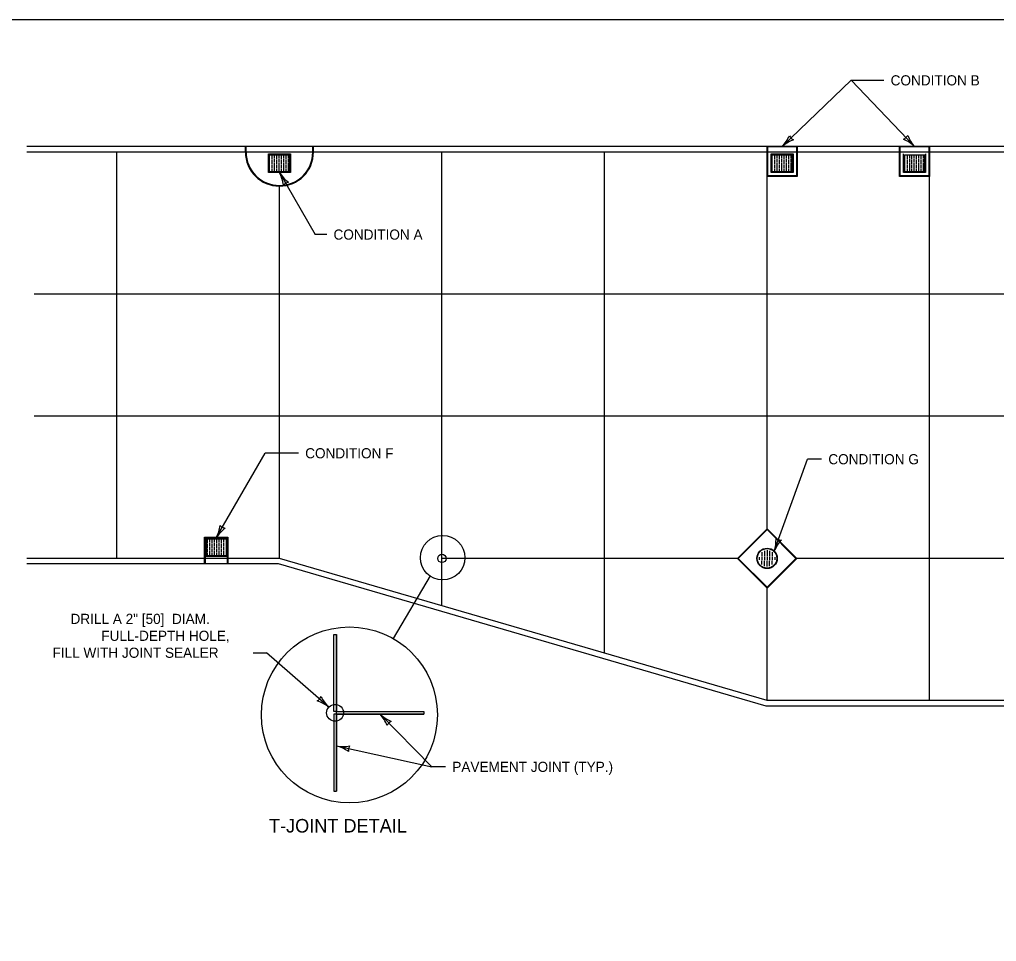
# Model space of a CAD drawing. Extents: x 49991.4 to 50029.7, y 49987.6 to 50011.4.
# Drawn here: x 49999.92 to 50005.69, y 49993.55 to 49999 of the extents above; entities that cross this region are included whole.
import ezdxf

# ---------------------------------------------------------------- set-up
doc = ezdxf.new("R2010")
doc.units = 0
for name, color, linetype in [('Level 1', 7, 'Continuous'), ('Level 18', 7, 'Continuous'), ('Level 2', 7, 'Continuous'), ('Level 3', 7, 'Continuous'), ('Level 62', 7, 'Continuous')]:
    doc.layers.add(name, color=color, linetype=linetype)

msp = doc.modelspace()

# ---------------------------------------------------------------- linework, layer by layer
at = {"layer": 'Level 1'}
for p, q in [((50005.8148, 49998.2482), (49999.9583, 49998.2482)), ((50005.8148, 49998.2157), (49999.9583, 49998.2157)), ((50000.4908, 49995.8157), (50000.4908, 49998.2157)), ((50001.25, 49998.2157), (50001.25, 49998.2482)), ((50001.2538, 49998.2157), (50001.2538, 49998.2482)), ((50001.6478, 49998.2157), (50001.6478, 49998.2482)), ((50001.6515, 49998.2157), (50001.6515, 49998.2482)), ((50002.4108, 49995.5357), (50002.4108, 49998.2157)), ((50003.3708, 49995.2557), (50003.3708, 49998.2157)), ((50004.3308, 49995.991), (50004.3308, 49998.2157)), ((50005.2908, 49994.9757), (50005.2908, 49998.2482)), ((50001.3858, 49998.0951), (50001.3858, 49998.2051)), ((50001.3858, 49998.2051), (50001.5158, 49998.2051)), ((50001.3901, 49998.2007), (50001.3901, 49998.0995)), ((50001.3908, 49998.1999), (50001.3901, 49998.2007)), ((50001.5114, 49998.2007), (50001.3901, 49998.2007)), ((50001.5108, 49998.1999), (50001.3908, 49998.1999)), ((50001.4063, 49998.1943), (50001.4063, 49998.1718)), ((50001.4063, 49998.1681), (50001.4063, 49998.1468)), ((50001.4199, 49998.1943), (50001.4199, 49998.1818)), ((50001.4199, 49998.178), (50001.4199, 49998.1568)), ((50001.4335, 49998.1943), (50001.4335, 49998.1718)), ((50001.4335, 49998.1681), (50001.4335, 49998.1468)), ((50001.4471, 49998.1943), (50001.4471, 49998.1818)), ((50001.4471, 49998.178), (50001.4471, 49998.1568)), ((50001.4607, 49998.1943), (50001.4607, 49998.1718)), ((50001.4607, 49998.1681), (50001.4607, 49998.1468)), ((50001.4743, 49998.1943), (50001.4743, 49998.1818)), ((50001.4743, 49998.178), (50001.4743, 49998.1568)), ((50001.4878, 49998.1943), (50001.4878, 49998.1718)), ((50001.4878, 49998.1681), (50001.4878, 49998.1468)), ((50001.5014, 49998.1943), (50001.5014, 49998.1818)), ((50001.5014, 49998.178), (50001.5014, 49998.1568)), ((50001.5114, 49998.2007), (50001.5108, 49998.1999)), ((50001.5108, 49998.0999), (50001.5108, 49998.1999)), ((50001.5114, 49998.0995), (50001.5114, 49998.2007)), ((50001.5158, 49998.2051), (50001.5158, 49998.0951)), ((50004.3545, 49998.0951), (50004.3545, 49998.2051)), ((50004.3545, 49998.2051), (50004.4845, 49998.2051)), ((50004.3589, 49998.2007), (50004.3589, 49998.0995)), ((50004.3595, 49998.1999), (50004.3589, 49998.2007)), ((50004.4801, 49998.2007), (50004.3589, 49998.2007)), ((50004.3751, 49998.1943), (50004.3751, 49998.1718)), ((50004.3751, 49998.1681), (50004.3751, 49998.1468)), ((50004.3886, 49998.1943), (50004.3886, 49998.1818)), ((50004.3886, 49998.178), (50004.3886, 49998.1568)), ((50004.4022, 49998.1943), (50004.4022, 49998.1718)), ((50004.4022, 49998.1681), (50004.4022, 49998.1468)), ((50004.4158, 49998.1943), (50004.4158, 49998.1818)), ((50004.4158, 49998.178), (50004.4158, 49998.1568)), ((50004.4294, 49998.1943), (50004.4294, 49998.1718)), ((50004.4294, 49998.1681), (50004.4294, 49998.1468)), ((50004.443, 49998.1943), (50004.443, 49998.1818)), ((50004.443, 49998.178), (50004.443, 49998.1568)), ((50004.4566, 49998.1943), (50004.4566, 49998.1718)), ((50004.4566, 49998.1681), (50004.4566, 49998.1468)), ((50004.4702, 49998.1943), (50004.4702, 49998.1818)), ((50004.4702, 49998.178), (50004.4702, 49998.1568)), ((50004.4801, 49998.2007), (50004.4795, 49998.1999)), ((50004.4795, 49998.0999), (50004.4795, 49998.1999)), ((50004.4801, 49998.0995), (50004.4801, 49998.2007)), ((50004.4845, 49998.2051), (50004.4845, 49998.0951)), ((50005.137, 49998.0951), (50005.137, 49998.2051)), ((50005.1414, 49998.2007), (50005.1414, 49998.0995)), ((50005.1576, 49998.1943), (50005.1576, 49998.1718)), ((50005.1576, 49998.1681), (50005.1576, 49998.1468)), ((50005.1711, 49998.1943), (50005.1711, 49998.1818)), ((50005.1711, 49998.178), (50005.1711, 49998.1568)), ((50005.1847, 49998.1943), (50005.1847, 49998.1718)), ((50005.1847, 49998.1681), (50005.1847, 49998.1468)), ((50005.1983, 49998.1943), (50005.1983, 49998.1818)), ((50005.1983, 49998.178), (50005.1983, 49998.1568)), ((50005.2119, 49998.1943), (50005.2119, 49998.1718)), ((50005.2119, 49998.1681), (50005.2119, 49998.1468)), ((50005.2255, 49998.1943), (50005.2255, 49998.1818)), ((50005.2255, 49998.178), (50005.2255, 49998.1568)), ((50005.2391, 49998.1943), (50005.2391, 49998.1718)), ((50005.2391, 49998.1681), (50005.2391, 49998.1468)), ((50005.2527, 49998.1943), (50005.2527, 49998.1818)), ((50005.2527, 49998.178), (50005.2527, 49998.1568)), ((50005.262, 49998.0999), (50005.262, 49998.1999)), ((50005.2626, 49998.0995), (50005.2626, 49998.2007)), ((50005.267, 49998.2051), (50005.267, 49998.0951)), ((50001.3908, 49998.0999), (50001.3901, 49998.0995)), ((50001.3901, 49998.0995), (50001.5114, 49998.0995)), ((50001.3908, 49998.0999), (50001.5108, 49998.0999)), ((50001.4063, 49998.1431), (50001.4063, 49998.1218)), ((50001.4063, 49998.1181), (50001.4063, 49998.1056)), ((50001.4199, 49998.1531), (50001.4199, 49998.1318)), ((50001.4199, 49998.1281), (50001.4199, 49998.1056)), ((50001.4335, 49998.1431), (50001.4335, 49998.1218)), ((50001.4335, 49998.1181), (50001.4335, 49998.1056)), ((50001.4471, 49998.1531), (50001.4471, 49998.1318)), ((50001.4471, 49998.1281), (50001.4471, 49998.1056)), ((50001.4607, 49998.1431), (50001.4607, 49998.1218)), ((50001.4607, 49998.1181), (50001.4607, 49998.1056)), ((50001.4743, 49998.1531), (50001.4743, 49998.1318)), ((50001.4743, 49998.1281), (50001.4743, 49998.1056)), ((50001.4876, 49998.0995), (50001.5101, 49998.0995)), ((50001.4878, 49998.1431), (50001.4878, 49998.1218)), ((50001.4878, 49998.1181), (50001.4878, 49998.1056)), ((50001.5014, 49998.1531), (50001.5014, 49998.1318)), ((50001.5014, 49998.1281), (50001.5014, 49998.1056)), ((50001.5114, 49998.0995), (50001.5108, 49998.0999)), ((50004.3595, 49998.0999), (50004.3589, 49998.0995)), ((50004.3589, 49998.0995), (50004.4801, 49998.0995)), ((50004.3595, 49998.0999), (50004.4795, 49998.0999)), ((50004.3751, 49998.1431), (50004.3751, 49998.1218)), ((50004.3751, 49998.1181), (50004.3751, 49998.1056)), ((50004.3886, 49998.1531), (50004.3886, 49998.1318)), ((50004.3886, 49998.1281), (50004.3886, 49998.1056)), ((50004.4022, 49998.1431), (50004.4022, 49998.1218)), ((50004.4022, 49998.1181), (50004.4022, 49998.1056)), ((50004.4158, 49998.1531), (50004.4158, 49998.1318)), ((50004.4158, 49998.1281), (50004.4158, 49998.1056)), ((50004.4294, 49998.1431), (50004.4294, 49998.1218)), ((50004.4294, 49998.1181), (50004.4294, 49998.1056)), ((50004.443, 49998.1531), (50004.443, 49998.1318)), ((50004.443, 49998.1281), (50004.443, 49998.1056)), ((50004.4563, 49998.0995), (50004.4789, 49998.0995)), ((50004.4566, 49998.1431), (50004.4566, 49998.1218)), ((50004.4566, 49998.1181), (50004.4566, 49998.1056)), ((50004.4702, 49998.1531), (50004.4702, 49998.1318)), ((50004.4702, 49998.1281), (50004.4702, 49998.1056)), ((50004.4801, 49998.0995), (50004.4795, 49998.0999)), ((50005.142, 49998.0999), (50005.1414, 49998.0995)), ((50005.1414, 49998.0995), (50005.2626, 49998.0995)), ((50005.142, 49998.0999), (50005.262, 49998.0999)), ((50005.1576, 49998.1431), (50005.1576, 49998.1218)), ((50005.1576, 49998.1181), (50005.1576, 49998.1056)), ((50005.1711, 49998.1531), (50005.1711, 49998.1318)), ((50005.1711, 49998.1281), (50005.1711, 49998.1056)), ((50005.1847, 49998.1431), (50005.1847, 49998.1218)), ((50005.1847, 49998.1181), (50005.1847, 49998.1056)), ((50005.1983, 49998.1531), (50005.1983, 49998.1318)), ((50005.1983, 49998.1281), (50005.1983, 49998.1056)), ((50005.2119, 49998.1431), (50005.2119, 49998.1218)), ((50005.2119, 49998.1181), (50005.2119, 49998.1056)), ((50005.2255, 49998.1531), (50005.2255, 49998.1318)), ((50005.2255, 49998.1281), (50005.2255, 49998.1056)), ((50005.2388, 49998.0995), (50005.2614, 49998.0995)), ((50005.2391, 49998.1431), (50005.2391, 49998.1218)), ((50005.2391, 49998.1181), (50005.2391, 49998.1056)), ((50005.2527, 49998.1531), (50005.2527, 49998.1318)), ((50005.2527, 49998.1281), (50005.2527, 49998.1056)), ((50005.2626, 49998.0995), (50005.262, 49998.0999)), ((50001.5158, 49998.0951), (50001.3858, 49998.0951)), ((50004.4845, 49998.0951), (50004.3545, 49998.0951)), ((50005.267, 49998.0951), (50005.137, 49998.0951)), ((50001.4508, 49995.8157), (50001.4508, 49998.015)), ((50016.2033, 49997.3757), (50000.0029, 49997.3757)), ((50011.8945, 49996.6557), (50000.0029, 49996.6557)), ((50001.0086, 49995.7832), (50001.0086, 49995.9401)), ((50001.0086, 49995.9401), (50001.1461, 49995.9401)), ((50001.0124, 49995.8264), (50001.0124, 49995.9363)), ((50001.0124, 49995.9363), (50001.1424, 49995.9363)), ((50001.0167, 49995.932), (50001.0174, 49995.9315)), ((50001.0167, 49995.932), (50001.0167, 49995.8307)), ((50001.138, 49995.932), (50001.0167, 49995.932)), ((50001.0174, 49995.9315), (50001.0174, 49995.8315)), ((50001.1374, 49995.9315), (50001.0174, 49995.9315)), ((50001.0406, 49995.932), (50001.018, 49995.932)), ((50001.0267, 49995.9034), (50001.0267, 49995.9259)), ((50001.0403, 49995.9134), (50001.0403, 49995.9259)), ((50001.0403, 49995.8884), (50001.0403, 49995.9096)), ((50001.0539, 49995.9034), (50001.0539, 49995.9259)), ((50001.0675, 49995.9134), (50001.0675, 49995.9259)), ((50001.0675, 49995.8884), (50001.0675, 49995.9096)), ((50001.0811, 49995.9034), (50001.0811, 49995.9259)), ((50001.0946, 49995.9134), (50001.0946, 49995.9259)), ((50001.0946, 49995.8884), (50001.0946, 49995.9096)), ((50001.1082, 49995.9034), (50001.1082, 49995.9259)), ((50001.1218, 49995.9134), (50001.1218, 49995.9259)), ((50001.1218, 49995.8884), (50001.1218, 49995.9096)), ((50001.1374, 49995.9315), (50001.138, 49995.932)), ((50001.138, 49995.8307), (50001.138, 49995.932)), ((50001.1424, 49995.9363), (50001.1424, 49995.8264)), ((50001.1461, 49995.9401), (50001.1461, 49995.7832)), ((50001.0267, 49995.8784), (50001.0267, 49995.8996)), ((50001.0267, 49995.8534), (50001.0267, 49995.8746)), ((50001.0267, 49995.8372), (50001.0267, 49995.8497)), ((50001.0403, 49995.8634), (50001.0403, 49995.8846)), ((50001.0403, 49995.8372), (50001.0403, 49995.8597)), ((50001.0539, 49995.8784), (50001.0539, 49995.8996)), ((50001.0539, 49995.8534), (50001.0539, 49995.8746)), ((50001.0539, 49995.8372), (50001.0539, 49995.8497)), ((50001.0675, 49995.8634), (50001.0675, 49995.8846)), ((50001.0675, 49995.8372), (50001.0675, 49995.8597)), ((50001.0811, 49995.8784), (50001.0811, 49995.8996)), ((50001.0811, 49995.8534), (50001.0811, 49995.8746)), ((50001.0811, 49995.8372), (50001.0811, 49995.8497)), ((50001.0946, 49995.8634), (50001.0946, 49995.8846)), ((50001.0947, 49995.8372), (50001.0947, 49995.8597)), ((50001.1082, 49995.8784), (50001.1082, 49995.8996)), ((50001.1082, 49995.8534), (50001.1082, 49995.8746)), ((50001.1082, 49995.8372), (50001.1082, 49995.8497)), ((50001.1218, 49995.8634), (50001.1218, 49995.8846)), ((50001.1218, 49995.8372), (50001.1218, 49995.8597)), ((50004.3001, 49995.8522), (50004.3001, 49995.8311)), ((50004.3154, 49995.8611), (50004.3154, 49995.8311)), ((50004.3308, 49995.8638), (50004.3308, 49995.8311)), ((50004.3461, 49995.8611), (50004.3461, 49995.8311)), ((50004.3614, 49995.8522), (50004.3614, 49995.8311)), ((50001.4508, 49995.8157), (49999.9583, 49995.8157)), ((50001.1424, 49995.8264), (50001.0124, 49995.8264)), ((50001.0124, 49995.8264), (50001.0124, 49995.7832)), ((50001.0167, 49995.8307), (50001.0174, 49995.8315)), ((50001.0167, 49995.8307), (50001.138, 49995.8307)), ((50001.1374, 49995.8315), (50001.138, 49995.8307)), ((50001.1424, 49995.8264), (50001.1424, 49995.7832)), ((50004.3308, 49994.9757), (50001.4508, 49995.8157)), ((50004.1554, 49995.8157), (50002.4108, 49995.8157)), ((50004.2848, 49995.8237), (50004.2848, 49995.8077)), ((50004.3001, 49995.8267), (50004.3001, 49995.8048)), ((50004.3001, 49995.7793), (50004.3001, 49995.8004)), ((50004.3154, 49995.8267), (50004.3154, 49995.8048)), ((50004.3154, 49995.7704), (50004.3154, 49995.8004)), ((50004.3308, 49995.8267), (50004.3308, 49995.8048)), ((50004.3308, 49995.7677), (50004.3308, 49995.8004)), ((50004.3461, 49995.8267), (50004.3461, 49995.8048)), ((50004.3461, 49995.7704), (50004.3461, 49995.8004)), ((50004.3614, 49995.8267), (50004.3614, 49995.8048)), ((50004.3614, 49995.7793), (50004.3614, 49995.8004)), ((50004.3767, 49995.8237), (50004.3767, 49995.8077)), ((50007.0905, 49995.8157), (50004.5061, 49995.8157)), ((50001.4461, 49995.7832), (49999.9583, 49995.7832)), ((50004.3261, 49994.9432), (50001.4461, 49995.7832)), ((50004.3308, 49994.9757), (50004.3308, 49995.6404)), ((50001.7718, 49994.9109), (50001.7718, 49995.3656)), ((50001.7874, 49994.9109), (50001.7874, 49995.3656)), ((50016.2033, 49994.9432), (50004.3261, 49994.9432)), ((50016.2033, 49994.9757), (50004.3308, 49994.9757)), ((50001.7718, 49994.8952), (50001.7718, 49994.4404)), ((50001.7874, 49994.9109), (50002.3028, 49994.9109)), ((50001.7874, 49994.8952), (50002.3028, 49994.8952)), ((50001.7874, 49994.8952), (50001.7874, 49994.4404))]:
    msp.add_line(p, q, dxfattribs=at)
for points in [[(49999.3835, 49998.9992), (50016.7501, 49998.9992), (50016.7501, 49987.7988), (49999.3835, 49987.7988)], [(50004.3308, 49998.2482), (50004.5083, 49998.2482), (50004.5083, 49998.0714), (50004.3308, 49998.0714)], [(50004.3345, 49998.2482), (50004.5045, 49998.2482), (50004.5045, 49998.0751), (50004.3345, 49998.0751)], [(50005.1133, 49998.2482), (50005.2908, 49998.2482), (50005.2908, 49998.0714), (50005.1133, 49998.0714)], [(50005.117, 49998.2482), (50005.287, 49998.2482), (50005.287, 49998.0751), (50005.117, 49998.0751)], [(50001.3908, 49998.1999), (50001.5107, 49998.1999), (50001.5107, 49998.0999), (50001.3908, 49998.0999)], [(50004.3595, 49998.1999), (50004.4795, 49998.1999), (50004.4795, 49998.0999), (50004.3595, 49998.0999)], [(50005.142, 49998.1999), (50005.262, 49998.1999), (50005.262, 49998.0999), (50005.142, 49998.0999)], [(50004.3308, 49995.991), (50004.5061, 49995.8157), (50004.3308, 49995.6404), (50004.1554, 49995.8157)], [(50004.3308, 49995.9857), (50004.5008, 49995.8157), (50004.3308, 49995.6457), (50004.1607, 49995.8157)], [(50001.1374, 49995.8315), (50001.0174, 49995.8315), (50001.0174, 49995.9315), (50001.1374, 49995.9315)], [(50001.7718, 49995.3656), (50001.7874, 49995.3656), (50001.7874, 49994.9109), (50001.7718, 49994.9109)], [(50001.7718, 49994.4404), (50001.7874, 49994.4404), (50001.7874, 49994.8952), (50001.7718, 49994.8952)], [(50002.3028, 49994.8952), (50001.7874, 49994.8952), (50001.7874, 49994.9109), (50002.3028, 49994.9109)]]:
    msp.add_lwpolyline(points, close=True, dxfattribs=at)
for centre, radius in [((50004.3308, 49995.8157), 0.0602), ((50004.3308, 49995.8157), 0.0577), ((50001.7796, 49994.903), 0.05)]:
    msp.add_circle(centre, radius, dxfattribs=at)
for radius in [0.2008, 0.197]:
    msp.add_arc((50001.4508, 49998.2157), radius, 180, 0, dxfattribs=at)
at = {"layer": 'Level 18'}
for p, q in [((50001.3908, 49998.1999), (50001.3908, 49998.0999)), ((50004.4795, 49998.1999), (50004.3595, 49998.1999)), ((50004.3595, 49998.1999), (50004.3595, 49998.0999)), ((50005.142, 49998.1999), (50005.142, 49998.0999)), ((50001.3858, 49998.0951), (50001.3858, 49998.0951)), ((50001.5158, 49998.0951), (50001.5158, 49998.0951)), ((50004.3545, 49998.0951), (50004.3545, 49998.0951)), ((50004.4845, 49998.0951), (50004.4845, 49998.0951)), ((50005.137, 49998.0951), (50005.137, 49998.0951)), ((50005.267, 49998.0951), (50005.267, 49998.0951)), ((50001.0124, 49995.9363), (50001.0124, 49995.9363)), ((50001.1374, 49995.8315), (50001.1374, 49995.9315)), ((50001.1424, 49995.9363), (50001.1424, 49995.9363)), ((50001.0174, 49995.8315), (50001.1374, 49995.8315))]:
    msp.add_line(p, q, dxfattribs=at)
at = {"layer": 'Level 3'}
for p, q in [((50004.8274, 49998.64), (50005.0206, 49998.64)), ((50001.4508, 49998.0951), (50001.6623, 49997.7288)), ((50001.7301, 49997.7288), (50001.6623, 49997.7288)), ((50001.0774, 49995.9363), (50001.3663, 49996.4368)), ((50001.5628, 49996.4368), (50001.3663, 49996.4368)), ((50004.3733, 49995.8583), (50004.5704, 49996.4016)), ((50004.6525, 49996.4016), (50004.5704, 49996.4016)), ((50002.3419, 49995.7121), (50002.1217, 49995.342)), ((50001.2952, 49995.2583), (50001.3752, 49995.2583)), ((50001.7423, 49994.9364), (50001.3752, 49995.2583)), ((50002.3516, 49994.5842), (50002.0451, 49994.8952)), ((50001.7874, 49994.7073), (50002.3516, 49994.5842)), ((50002.4316, 49994.5842), (50002.3516, 49994.5842))]:
    msp.add_line(p, q, dxfattribs=at)
msp.add_lwpolyline([(50004.4195, 49998.2482), (50004.8274, 49998.64), (50005.202, 49998.2482)], dxfattribs=at)
for centre, radius in [((50002.4147, 49995.8195), 0.1314), ((50001.8639, 49994.8912), 0.5198)]:
    msp.add_circle(centre, radius, dxfattribs=at)
for centre, radius, start, end in [((50004.25, 49998.4081), 0.233, 316.67449, 335.92434), ((50004.5668, 49998.0817), 0.2223, 111.30319, 131.4867), ((50004.512, 49998.337), 0.0548, 205.986, 241.70836), ((50005.1134, 49998.3409), 0.0548, 295.85488, 331.57724), ((50005.0418, 49998.0791), 0.233, 46.54337, 65.79322), ((50005.3689, 49998.3951), 0.2223, 201.17207, 221.35558), ((50001.2538, 49997.992), 0.2223, 7.45601, 27.63952), ((50001.6466, 49998.2214), 0.233, 212.82731, 232.07716), ((50001.5149, 49997.9841), 0.0548, 102.13882, 137.86118), ((50000.8701, 49996.0427), 0.233, 332.82732, 352.07717), ((50001.2652, 49995.8173), 0.2223, 127.45602, 147.63953), ((50001.1415, 49996.0474), 0.0548, 222.13883, 257.86119), ((50004.1507, 49995.9268), 0.233, 342.89595, 2.1458), ((50004.5791, 49995.774), 0.2223, 137.52465, 157.70816), ((50004.4171, 49995.9788), 0.0548, 232.20746, 267.92982), ((50001.6459, 49995.0209), 0.0548, 300.9002, 336.62256), ((50001.8957, 49995.0974), 0.2223, 206.21739, 226.4009), ((50001.5976, 49994.7538), 0.233, 51.58869, 70.83854), ((50001.8804, 49994.7458), 0.2223, 22.03482, 42.21833), ((50002.2028, 49995.0668), 0.233, 227.40612, 246.65597), ((50002.1351, 49994.8039), 0.0548, 116.71763, 152.43999), ((50001.8258, 49994.9371), 0.233, 260.52278, 279.77263), ((50001.7311, 49994.4922), 0.2223, 55.15148, 75.33498), ((50001.9127, 49994.6799), 0.0548, 149.83428, 185.55665)]:
    msp.add_arc(centre, radius, start, end, dxfattribs=at)
at = {"layer": 'Level 62'}
msp.add_circle((50002.4108, 49995.8157), 0.025, dxfattribs=at)

# ---------------------------------------------------------------- texts
at = {"layer": 'Level 2'}
for s, height, p in [('CONDITION B', 0.06, (50005.0606, 49998.61)), ('CONDITION A', 0.06, (50001.7701, 49997.6988)), ('CONDITION F', 0.06, (50001.6028, 49996.4068)), ('CONDITION G', 0.06, (50004.6925, 49996.3716)), ('DRILL A 2" [50]  DIAM. ', 0.06, (50000.2169, 49995.4283)), ('FULL-DEPTH HOLE, ', 0.06, (50000.3988, 49995.3283)), ('FILL WITH JOINT SEALER', 0.06, (50000.1105, 49995.2283)), ('PAVEMENT JOINT (TYP.)', 0.06, (50002.4716, 49994.5542)), ('T-JOINT DETAIL', 0.08, (50001.389, 49994.196))]:
    msp.add_text(s, height=height, dxfattribs=at).set_placement(p)

doc.saveas('drawing.dxf')
